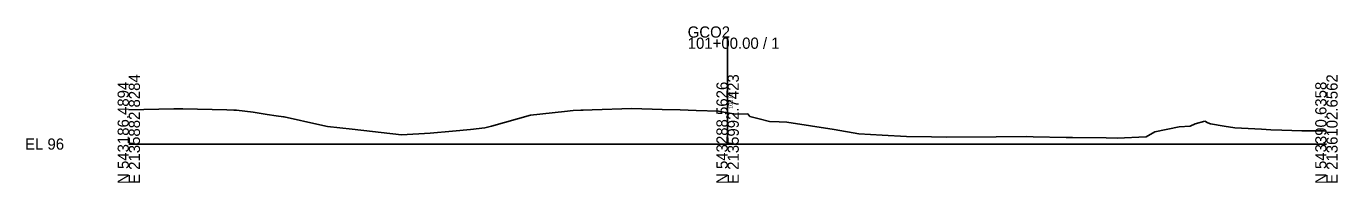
# Model space of a CAD drawing. Extents: x -14327 to 8886, y -10 to 39048.
# Drawn here: x 3974.3 to 4302.8, y 21990.3 to 22029.5 of the extents above; entities that cross this region are included whole.
import ezdxf

# ---------------------------------------------------------------- set-up
doc = ezdxf.new("R2010")
doc.units = 0
for name, color, linetype in [('RD_GPK_XS_Cell', 7, 'Continuous'), ('RD_XS_ExGround', 7, 'Continuous'), ('RD_XS_TX_Elev_EX', 7, 'Continuous')]:
    doc.layers.add(name, color=color, linetype=linetype)

msp = doc.modelspace()

# ---------------------------------------------------------------- linework, layer by layer
at = {"layer": 'RD_GPK_XS_Cell'}
for p, q in [((4150, 22000), (4150, 22026.66)), ((4000, 22000), (4150, 22000)), ((4150, 22000), (4300, 22000))]:
    msp.add_line(p, q, dxfattribs=at)
at = {"layer": 'RD_XS_ExGround'}
for p, q in [((4000, 22008.6), (4000.04, 22008.6)), ((4000.04, 22008.6), (4011.31, 22008.84)), ((4011.31, 22008.84), (4012.02, 22008.85)), ((4012.02, 22008.85), (4013.54, 22008.82)), ((4013.54, 22008.82), (4024.59, 22008.53)), ((4024.59, 22008.53), (4026.28, 22008.48)), ((4026.28, 22008.48), (4027, 22008.46)), ((4027, 22008.46), (4031.12, 22007.98)), ((4111.29, 22008.39), (4113.27, 22008.47)), ((4113.27, 22008.47), (4113.84, 22008.48)), ((4113.84, 22008.48), (4116.05, 22008.56)), ((4116.05, 22008.56), (4126.04, 22008.89)), ((4126.04, 22008.89), (4133.61, 22008.68)), ((4133.61, 22008.68), (4138.15, 22008.55)), ((4138.15, 22008.55), (4142.1, 22008.42)), ((4142.1, 22008.42), (4147.68, 22008.21)), ((4031.12, 22007.98), (4034.63, 22007.43)), ((4034.63, 22007.43), (4036.94, 22007.08)), ((4036.94, 22007.08), (4038.72, 22006.85)), ((4038.72, 22006.85), (4038.89, 22006.79)), ((4038.89, 22006.79), (4047.86, 22004.84)), ((4090.86, 22004.49), (4100.65, 22007.21)), ((4100.65, 22007.21), (4109.15, 22008.12)), ((4109.15, 22008.12), (4111.29, 22008.39)), ((4147.68, 22008.21), (4150, 22007.82)), ((4150, 22007.82), (4152.09, 22007.46)), ((4152.09, 22007.46), (4155.1, 22007.58)), ((4155.1, 22007.58), (4155.59, 22006.88)), ((4155.59, 22006.88), (4157.92, 22006.29)), ((4157.92, 22006.29), (4160.48, 22005.61)), ((4160.48, 22005.61), (4162.91, 22005.57)), ((4162.91, 22005.57), (4164.82, 22005.47)), ((4164.82, 22005.47), (4176.72, 22003.64)), ((4267.14, 22005.07), (4269.58, 22005.77)), ((4269.58, 22005.77), (4270.27, 22005.31)), ((4270.27, 22005.31), (4270.93, 22005.06)), ((4047.86, 22004.84), (4049.75, 22004.38)), ((4049.75, 22004.38), (4055.99, 22003.71)), ((4055.99, 22003.71), (4068.3, 22002.3)), ((4068.3, 22002.3), (4075.53, 22002.76)), ((4075.53, 22002.76), (4081.11, 22003.26)), ((4081.11, 22003.26), (4085.63, 22003.65)), ((4085.63, 22003.65), (4089.18, 22004.04)), ((4089.18, 22004.04), (4090.86, 22004.49)), ((4176.72, 22003.64), (4182.86, 22002.6)), ((4182.86, 22002.6), (4188.73, 22002.19)), ((4188.73, 22002.19), (4194.83, 22001.88)), ((4194.83, 22001.88), (4201.03, 22001.82)), ((4217.28, 22001.79), (4224.84, 22001.89)), ((4224.84, 22001.89), (4226.57, 22001.77)), ((4254.84, 22001.82), (4257.02, 22003.05)), ((4257.02, 22003.05), (4263.15, 22004.34)), ((4263.15, 22004.34), (4265.83, 22004.52)), ((4265.83, 22004.52), (4267.14, 22005.07)), ((4270.93, 22005.06), (4274.35, 22004.49)), ((4274.35, 22004.49), (4277.02, 22004.1)), ((4277.02, 22004.1), (4283.72, 22003.73)), ((4283.72, 22003.73), (4286.11, 22003.59)), ((4286.11, 22003.59), (4288.85, 22003.52)), ((4288.85, 22003.52), (4293.8, 22003.29)), ((4293.8, 22003.29), (4299.36, 22003.28)), ((4299.36, 22003.28), (4300, 22003.25)), ((4201.03, 22001.82), (4204.83, 22001.76)), ((4204.83, 22001.76), (4217.28, 22001.79)), ((4226.57, 22001.77), (4234.84, 22001.64)), ((4234.84, 22001.64), (4236.38, 22001.65)), ((4236.38, 22001.65), (4244.84, 22001.55)), ((4244.84, 22001.55), (4247.61, 22001.47)), ((4247.61, 22001.47), (4254.84, 22001.82))]:
    msp.add_line(p, q, dxfattribs=at)

# ---------------------------------------------------------------- texts
at = {"layer": 'RD_GPK_XS_Cell'}
for s, p in [('GCO2', (4140, 22026.66)), ('101+00.00 / 1', (4140, 22023.86)), ('EL 96', (3974, 21998.6))]:
    msp.add_text(s, height=2.8, dxfattribs=at).set_placement(p)
for s, p in [('N 543186.4894', (4000, 21990)), ('E 2135882.8284', (4002.8, 21990)), ('N 543288.5626', (4150, 21990)), ('E 2135992.7423', (4152.8, 21990)), ('N 543390.6358', (4300, 21990)), ('E 2136102.6562', (4302.8, 21990))]:
    msp.add_text(s, height=2.8, rotation=90, dxfattribs=at).set_placement(p)
at = {"layer": 'RD_XS_TX_Elev_EX'}
msp.add_text('103.82', height=1, rotation=90, dxfattribs=at).set_placement((4151.25, 22008.82))

doc.saveas('drawing.dxf')
